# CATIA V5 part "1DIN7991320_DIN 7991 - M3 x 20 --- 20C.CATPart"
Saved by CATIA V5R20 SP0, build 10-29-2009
Part number: 1DIN7991320_DIN 7991 - M3 x 20 --- 20C
Revision: ANY
Definition: UNKNOWN
Nomenclature: 1DIN7991320_DIN 7991 - M3 x 20 --- 20C
Source: Unknown
Bounding box of the stored display mesh (mm): x 0 to 20, y -2.711 to 2.711, z -2.85 to 2.85
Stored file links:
  C:\Users\Utente\Desktop\IO LAVORO\3D X SITO CF\CUMSA\3D files PO\PO 120320\1DIN7991320_DIN 7991 - M3 x 20 --- 20C.CATPart
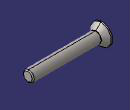
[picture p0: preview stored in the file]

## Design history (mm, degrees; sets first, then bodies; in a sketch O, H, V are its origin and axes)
Body1 "Hex" (main body)
  Solid1: solid without history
